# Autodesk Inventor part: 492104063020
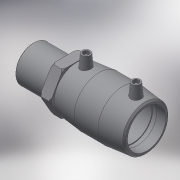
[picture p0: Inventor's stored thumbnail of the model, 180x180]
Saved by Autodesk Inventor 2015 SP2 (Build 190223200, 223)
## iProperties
Created: 2017-06
Part Number: 492104063020
Material: Generic
Description: PLASSON Male Transition Coupler 63 x 2"
Document SubType Name: Modeling
Designer: KIM
Mass: 350.228 g
Surface Area: 772.919 cm^2
Volume: 350.228 cm^3
Density: 1 g/cm^3
Appearance: Default
Author: KIM
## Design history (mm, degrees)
derived "492104.ipt"
feature "Solid1::492104.ipt"
tag "TaggingFeature1"
body "Solid1"
other parameters: "d0" = 117, "d1" = 63, "d2" = 82, "d3" = 57, "d4" = 39, "d5" = 73.8, "d6" = 59.85, "d7" = 63, "d8" = 168 deg, "d10" = 22.8, "d11" = 7.6, "d29" = 57, "d30" = 14, "d31" = 40.95, "d34" = 5 deg, "d41" = 4, "d42" = 14, "d43" = 0, "d48" = 3, "d49" = 0, "d57" = 48, "d58" = 59.614, "d59" = 47.6912, "d60" = 36.9, "d61" = 82, "d62" = 1.19228, "d65" = 2.46, "d70" = 0.1, "d71" = 41, "d72" = 10.25, "d73" = 22.8, "d75" = 0, "d_" = 63, "L_" = 158, "L_1" = 57, "D_1" = 82, "A_" = 57, "d_2" = 12, "L_2" = 41, "D_" = 48, "R_" = 59.614
